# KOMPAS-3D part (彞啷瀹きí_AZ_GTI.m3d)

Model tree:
1. Эскиз:1
2. Операция выдавливания:2
     Расстояние 1 = 17
3. Эскиз:2
4. Вырезать элемент выдавливания:1
     Расстояние 1 = 7
5. Эскиз:3
6. Операция выдавливания:3
     Расстояние 1 = 5
7. Эскиз:4
8. Отверстие:1
9. Эскиз:6
10. Отверстие:2  (labels: H1)
11. Массив по концентрической сетке:1  (with: Отверстие:2)  (labels: Экземпляр ( 1, 1 ); Экземпляр ( 1, 2 ); Экземпляр ( 1, 3 ); Экземпляр ( 1, 4 ))
     N 2 = 4; Шаг 2 = 360
12. Эскиз:8
13. Эскиз:9
14. Отверстие:3
15. Эскиз:10
16. Отверстие:4

Referenced files in C:\Program Files (x86)\ASCON\KOMPAS-3D LT V12\Sys\: holelib.lfr
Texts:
  Отверстие 01
  Отверстие 07
  (вариант 1)
  Отверстие с цековкой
